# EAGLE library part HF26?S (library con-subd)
SUB-D
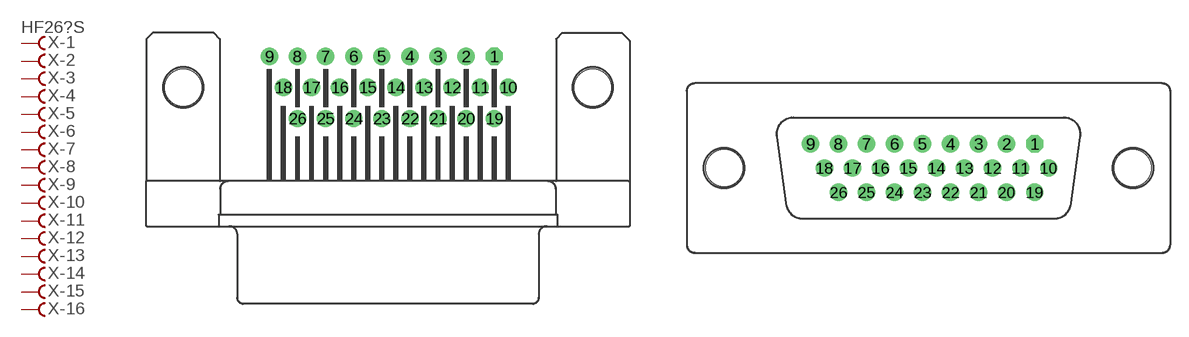
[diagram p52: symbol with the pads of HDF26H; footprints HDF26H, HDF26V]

Designator prefix X; gates -1=FV -2=F -3=F -4=F -5=F -6=F -7=F -8=F -9=F -10=F -11=F -12=F -13=F -14=F -15=F -16=F -17=F -18=F -19=F -20=F -21=F -22=F -23=F -24=F -25=F -26=F

## HF26HS (OC_FARNELL: unknown; OC_NEWARK: unknown)  [HDF26H]
1  -1:F  pas
2  -2:F  pas
3  -3:F  pas
4  -4:F  pas
5  -5:F  pas
6  -6:F  pas
7  -7:F  pas
8  -8:F  pas
9  -9:F  pas
10  -10:F  pas
11  -11:F  pas
12  -12:F  pas
13  -13:F  pas
14  -14:F  pas
15  -15:F  pas
16  -16:F  pas
17  -17:F  pas
18  -18:F  pas
19  -19:F  pas
20  -20:F  pas
21  -21:F  pas
22  -22:F  pas
23  -23:F  pas
24  -24:F  pas
25  -25:F  pas
26  -26:F  pas

## HF26VS (OC_FARNELL: unknown; OC_NEWARK: unknown)  [HDF26V]
Pads as for HDF26H

## Footprint HDF26H (pad centres in mm)
SUB-D
drill 0.9 octagon: 1 8.639,2.54
drill 0.9 round: 2 6.353,2.54; 3 4.067,2.54; 4 1.781,2.54; 5 -0.505,2.54; 6 -2.791,2.54; 7 -5.077,2.54; 8 -7.363,2.54; 9 -9.649,2.54; 10 9.782,0; 11 7.496,0; 12 5.21,0; 13 2.924,0; 14 0.638,0; 15 -1.648,0; 16 -3.934,0; 17 -6.22,0; 18 -8.506,0; 19 8.639,-2.54; 20 6.353,-2.54; 21 4.067,-2.54; 22 1.781,-2.54; 23 -0.505,-2.54; 24 -2.791,-2.54; 25 -5.077,-2.54; 26 -7.363,-2.54
hole 3 at -16.65,0
hole 3 at 16.65,0

## Footprint HDF26V (pad centres in mm)
SUB-D
drill 0.9 octagon: 1 8.658,1.98
drill 0.9 round: 2 6.372,1.98; 3 4.086,1.98; 4 1.8,1.98; 5 -0.486,1.98; 6 -2.772,1.98; 7 -5.058,1.98; 8 -7.344,1.98; 9 -9.63,1.98; 10 9.801,0; 11 7.515,0; 12 5.229,0; 13 2.943,0; 14 0.657,0; 15 -1.629,0; 16 -3.915,0; 17 -6.201,0; 18 -8.487,0; 19 8.658,-1.98; 20 6.372,-1.98; 21 4.086,-1.98; 22 1.8,-1.98; 23 -0.486,-1.98; 24 -2.772,-1.98; 25 -5.058,-1.98; 26 -7.344,-1.98
hole 3 at -16.65,0
hole 3 at 16.65,0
